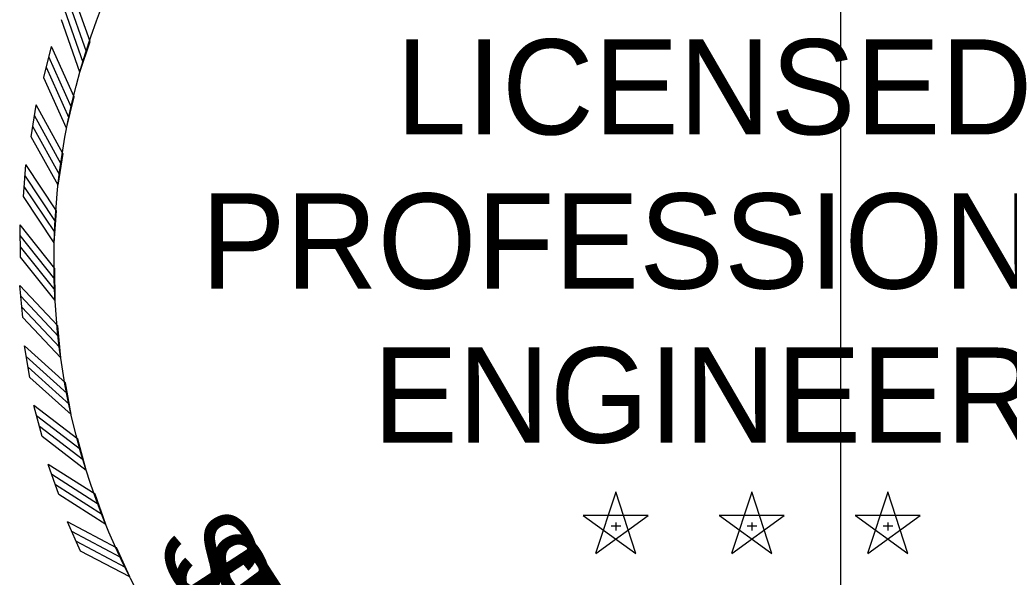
# Model space of a CAD drawing. Extents: x 18 to 14744716, y -5 to 1829144.
# Drawn here: x 17.6804 to 17.7967, y 10.8689 to 10.9344 of the extents above; entities that cross this region are included whole.
import ezdxf

# ---------------------------------------------------------------- set-up
doc = ezdxf.new("R2010")
doc.units = 0
for name, color, linetype in [('B_StampERBB', 7, 'Continuous'), ('B_StampHSS', 7, 'Continuous'), ('B_StampJSB', 7, 'Continuous'), ('B_StampSCR', 7, 'Continuous'), ('B_StampSFH', 7, 'Continuous'), ('R_No Plot', 7, 'Continuous')]:
    doc.layers.add(name, color=color, linetype=linetype)

msp = doc.modelspace()

# ---------------------------------------------------------------- linework, layer by layer
at = {"layer": 'B_StampERBB'}
for p, q in [((17.6832, 10.92765), (17.68409, 10.93131)), ((17.68744, 10.9283), (17.68864, 10.93188)), ((17.68588, 10.9217), (17.68678, 10.92537)), ((17.68171, 10.9207), (17.68229, 10.92442)), ((17.68487, 10.91499), (17.68546, 10.91873)), ((17.68079, 10.91365), (17.68107, 10.91741)), ((17.68442, 10.90823), (17.68469, 10.912)), ((17.68046, 10.90655), (17.68043, 10.91032)), ((17.68452, 10.90145), (17.68449, 10.90522)), ((17.68072, 10.89945), (17.68037, 10.90321)), ((17.68519, 10.8947), (17.68484, 10.89846)), ((17.68156, 10.8924), (17.68091, 10.89611)), ((17.68641, 10.88803), (17.68575, 10.89175)), ((17.68299, 10.88543), (17.68203, 10.88908)), ((17.68817, 10.88148), (17.68721, 10.88513)), ((17.68498, 10.87861), (17.68372, 10.88217)), ((17.69048, 10.8751), (17.68922, 10.87866)), ((17.75045, 10.87892), (17.74809, 10.87168)), ((17.7528, 10.87168), (17.75045, 10.87893)), ((17.76644, 10.87892), (17.76408, 10.87168)), ((17.76879, 10.87168), (17.76644, 10.87893)), ((17.78243, 10.87892), (17.78007, 10.87168)), ((17.78478, 10.87168), (17.78243, 10.87893)), ((17.68753, 10.87198), (17.68598, 10.87542)), ((17.75425, 10.87615), (17.74664, 10.87616)), ((17.74664, 10.87615), (17.7528, 10.87168)), ((17.7481, 10.87168), (17.75426, 10.87615)), ((17.75045, 10.87534), (17.75045, 10.87439)), ((17.77024, 10.87615), (17.76263, 10.87616)), ((17.76264, 10.87615), (17.76879, 10.87168)), ((17.76409, 10.87168), (17.77025, 10.87615)), ((17.76645, 10.87534), (17.76645, 10.87439)), ((17.78623, 10.87615), (17.77862, 10.87616)), ((17.77863, 10.87615), (17.78478, 10.87168)), ((17.78008, 10.87168), (17.78624, 10.87615)), ((17.78244, 10.87534), (17.78244, 10.87439)), ((17.7499, 10.87494), (17.75104, 10.87494)), ((17.7659, 10.87494), (17.76703, 10.87494)), ((17.78189, 10.87494), (17.78302, 10.87494)), ((17.6933, 10.86893), (17.69175, 10.87238))]:
    msp.add_line(p, q, dxfattribs=at)
for points in [[(17.68863, 10.93188), (17.68645, 10.93803)], [(17.68823, 10.93069), (17.68605, 10.93684)], [(17.68784, 10.92944), (17.68566, 10.93559)], [(17.68745, 10.92829), (17.68527, 10.93444)], [(17.68677, 10.92537), (17.68409, 10.93131)], [(17.68646, 10.92415), (17.68378, 10.9301)], [(17.68618, 10.92287), (17.6835, 10.92882)], [(17.68588, 10.92169), (17.6832, 10.92764)], [(17.68545, 10.91872), (17.68229, 10.92443)], [(17.68525, 10.91748), (17.68209, 10.92319)], [(17.68507, 10.91619), (17.68191, 10.92189)], [(17.68487, 10.91499), (17.68171, 10.92069)], [(17.68469, 10.91199), (17.68107, 10.91742)], [(17.68459, 10.91074), (17.68096, 10.91616)], [(17.68452, 10.90943), (17.6809, 10.91486)], [(17.68442, 10.90822), (17.6808, 10.91365)], [(17.68448, 10.90522), (17.68043, 10.91033)], [(17.68448, 10.90396), (17.68043, 10.90907)], [(17.68453, 10.90266), (17.68047, 10.90776)], [(17.68453, 10.90144), (17.68047, 10.90655)], [(17.68484, 10.89846), (17.68037, 10.90321)], [(17.68494, 10.8972), (17.68048, 10.90196)], [(17.68509, 10.8959), (17.68062, 10.90066)], [(17.68519, 10.89469), (17.68072, 10.89945)], [(17.68575, 10.89174), (17.68091, 10.89611)], [(17.68596, 10.8905), (17.68111, 10.89487)], [(17.68621, 10.88922), (17.68137, 10.89359)], [(17.68641, 10.88802), (17.68157, 10.89239)], [(17.68721, 10.88513), (17.68202, 10.88908)], [(17.68752, 10.88391), (17.68233, 10.88786)], [(17.68788, 10.88265), (17.68269, 10.88661)], [(17.68818, 10.88147), (17.68299, 10.88543)], [(17.68922, 10.87866), (17.68372, 10.88217)], [(17.68962, 10.87747), (17.68413, 10.88098)], [(17.69009, 10.87624), (17.68459, 10.87976)], [(17.69048, 10.8751), (17.68498, 10.87861)], [(17.69175, 10.87237), (17.68598, 10.87542)], [(17.69225, 10.87122), (17.68648, 10.87427)], [(17.69282, 10.87004), (17.68705, 10.87309)], [(17.6933, 10.86893), (17.68753, 10.87197)]]:
    msp.add_lwpolyline(points, dxfattribs=at)
at = {"layer": 'B_StampHSS'}
for p, q in [((17.6832, 10.92765), (17.68409, 10.93131)), ((17.68744, 10.9283), (17.68864, 10.93188)), ((17.68588, 10.9217), (17.68678, 10.92537)), ((17.68171, 10.9207), (17.68229, 10.92442)), ((17.68487, 10.91499), (17.68546, 10.91873)), ((17.68079, 10.91365), (17.68107, 10.91741)), ((17.68442, 10.90823), (17.68469, 10.912)), ((17.68046, 10.90655), (17.68043, 10.91032)), ((17.68452, 10.90145), (17.68449, 10.90522)), ((17.68072, 10.89945), (17.68037, 10.90321)), ((17.68519, 10.8947), (17.68484, 10.89846)), ((17.68156, 10.8924), (17.68091, 10.89611)), ((17.68641, 10.88803), (17.68575, 10.89175)), ((17.68299, 10.88543), (17.68203, 10.88908)), ((17.68817, 10.88148), (17.68721, 10.88513)), ((17.68498, 10.87861), (17.68372, 10.88217)), ((17.69048, 10.8751), (17.68922, 10.87866)), ((17.75045, 10.87892), (17.74809, 10.87168)), ((17.7528, 10.87168), (17.75045, 10.87893)), ((17.76644, 10.87892), (17.76408, 10.87168)), ((17.76879, 10.87168), (17.76644, 10.87893)), ((17.78243, 10.87892), (17.78007, 10.87168)), ((17.78478, 10.87168), (17.78243, 10.87893)), ((17.68753, 10.87198), (17.68598, 10.87542)), ((17.75425, 10.87615), (17.74664, 10.87616)), ((17.74664, 10.87615), (17.7528, 10.87168)), ((17.7481, 10.87168), (17.75426, 10.87615)), ((17.75045, 10.87534), (17.75045, 10.87439)), ((17.77024, 10.87615), (17.76263, 10.87616)), ((17.76264, 10.87615), (17.76879, 10.87168)), ((17.76409, 10.87168), (17.77025, 10.87615)), ((17.76645, 10.87534), (17.76645, 10.87439)), ((17.78623, 10.87615), (17.77862, 10.87616)), ((17.77863, 10.87615), (17.78478, 10.87168)), ((17.78008, 10.87168), (17.78624, 10.87615)), ((17.78244, 10.87534), (17.78244, 10.87439)), ((17.7499, 10.87494), (17.75104, 10.87494)), ((17.7659, 10.87494), (17.76703, 10.87494)), ((17.78189, 10.87494), (17.78302, 10.87494)), ((17.6933, 10.86893), (17.69175, 10.87238))]:
    msp.add_line(p, q, dxfattribs=at)
for points in [[(17.68863, 10.93188), (17.68645, 10.93803)], [(17.68823, 10.93069), (17.68605, 10.93684)], [(17.68784, 10.92944), (17.68566, 10.93559)], [(17.68745, 10.92829), (17.68527, 10.93444)], [(17.68677, 10.92537), (17.68409, 10.93131)], [(17.68646, 10.92415), (17.68378, 10.9301)], [(17.68618, 10.92287), (17.6835, 10.92882)], [(17.68588, 10.92169), (17.6832, 10.92764)], [(17.68545, 10.91872), (17.68229, 10.92443)], [(17.68525, 10.91748), (17.68209, 10.92319)], [(17.68507, 10.91619), (17.68191, 10.92189)], [(17.68487, 10.91499), (17.68171, 10.92069)], [(17.68469, 10.91199), (17.68107, 10.91742)], [(17.68459, 10.91074), (17.68096, 10.91616)], [(17.68452, 10.90943), (17.6809, 10.91486)], [(17.68442, 10.90822), (17.6808, 10.91365)], [(17.68448, 10.90522), (17.68043, 10.91033)], [(17.68448, 10.90396), (17.68043, 10.90907)], [(17.68453, 10.90266), (17.68047, 10.90776)], [(17.68453, 10.90144), (17.68047, 10.90655)], [(17.68484, 10.89846), (17.68037, 10.90321)], [(17.68494, 10.8972), (17.68048, 10.90196)], [(17.68509, 10.8959), (17.68062, 10.90066)], [(17.68519, 10.89469), (17.68072, 10.89945)], [(17.68575, 10.89174), (17.68091, 10.89611)], [(17.68596, 10.8905), (17.68111, 10.89487)], [(17.68621, 10.88922), (17.68137, 10.89359)], [(17.68641, 10.88802), (17.68157, 10.89239)], [(17.68721, 10.88513), (17.68202, 10.88908)], [(17.68752, 10.88391), (17.68233, 10.88786)], [(17.68788, 10.88265), (17.68269, 10.88661)], [(17.68818, 10.88147), (17.68299, 10.88543)], [(17.68922, 10.87866), (17.68372, 10.88217)], [(17.68962, 10.87747), (17.68413, 10.88098)], [(17.69009, 10.87624), (17.68459, 10.87976)], [(17.69048, 10.8751), (17.68498, 10.87861)], [(17.69175, 10.87237), (17.68598, 10.87542)], [(17.69225, 10.87122), (17.68648, 10.87427)], [(17.69282, 10.87004), (17.68705, 10.87309)], [(17.6933, 10.86893), (17.68753, 10.87197)]]:
    msp.add_lwpolyline(points, dxfattribs=at)
at = {"layer": 'B_StampJSB'}
for p, q in [((17.6832, 10.92765), (17.68409, 10.93131)), ((17.68744, 10.9283), (17.68864, 10.93188)), ((17.68588, 10.9217), (17.68678, 10.92537)), ((17.68171, 10.9207), (17.68229, 10.92442)), ((17.68487, 10.91499), (17.68546, 10.91873)), ((17.68079, 10.91365), (17.68107, 10.91741)), ((17.68442, 10.90823), (17.68469, 10.912)), ((17.68046, 10.90655), (17.68043, 10.91032)), ((17.68452, 10.90145), (17.68449, 10.90522)), ((17.68072, 10.89945), (17.68037, 10.90321)), ((17.68519, 10.8947), (17.68484, 10.89846)), ((17.68156, 10.8924), (17.68091, 10.89611)), ((17.68641, 10.88803), (17.68575, 10.89175)), ((17.68299, 10.88543), (17.68203, 10.88908)), ((17.68817, 10.88148), (17.68721, 10.88513)), ((17.68498, 10.87861), (17.68372, 10.88217)), ((17.69048, 10.8751), (17.68922, 10.87866)), ((17.75045, 10.87892), (17.74809, 10.87168)), ((17.7528, 10.87168), (17.75045, 10.87893)), ((17.76644, 10.87892), (17.76408, 10.87168)), ((17.76879, 10.87168), (17.76644, 10.87893)), ((17.78243, 10.87892), (17.78007, 10.87168)), ((17.78478, 10.87168), (17.78243, 10.87893)), ((17.68753, 10.87198), (17.68598, 10.87542)), ((17.75425, 10.87615), (17.74664, 10.87616)), ((17.74664, 10.87615), (17.7528, 10.87168)), ((17.7481, 10.87168), (17.75426, 10.87615)), ((17.75045, 10.87534), (17.75045, 10.87439)), ((17.77024, 10.87615), (17.76263, 10.87616)), ((17.76264, 10.87615), (17.76879, 10.87168)), ((17.76409, 10.87168), (17.77025, 10.87615)), ((17.76645, 10.87534), (17.76645, 10.87439)), ((17.78623, 10.87615), (17.77862, 10.87616)), ((17.77863, 10.87615), (17.78478, 10.87168)), ((17.78008, 10.87168), (17.78624, 10.87615)), ((17.78244, 10.87534), (17.78244, 10.87439)), ((17.7499, 10.87494), (17.75104, 10.87494)), ((17.7659, 10.87494), (17.76703, 10.87494)), ((17.78189, 10.87494), (17.78302, 10.87494)), ((17.6933, 10.86893), (17.69175, 10.87238))]:
    msp.add_line(p, q, dxfattribs=at)
for points in [[(17.68863, 10.93188), (17.68645, 10.93803)], [(17.68823, 10.93069), (17.68605, 10.93684)], [(17.68784, 10.92944), (17.68566, 10.93559)], [(17.68745, 10.92829), (17.68527, 10.93444)], [(17.68677, 10.92537), (17.68409, 10.93131)], [(17.68646, 10.92415), (17.68378, 10.9301)], [(17.68618, 10.92287), (17.6835, 10.92882)], [(17.68588, 10.92169), (17.6832, 10.92764)], [(17.68545, 10.91872), (17.68229, 10.92443)], [(17.68525, 10.91748), (17.68209, 10.92319)], [(17.68507, 10.91619), (17.68191, 10.92189)], [(17.68487, 10.91499), (17.68171, 10.92069)], [(17.68469, 10.91199), (17.68107, 10.91742)], [(17.68459, 10.91074), (17.68096, 10.91616)], [(17.68452, 10.90943), (17.6809, 10.91486)], [(17.68442, 10.90822), (17.6808, 10.91365)], [(17.68448, 10.90522), (17.68043, 10.91033)], [(17.68448, 10.90396), (17.68043, 10.90907)], [(17.68453, 10.90266), (17.68047, 10.90776)], [(17.68453, 10.90144), (17.68047, 10.90655)], [(17.68484, 10.89846), (17.68037, 10.90321)], [(17.68494, 10.8972), (17.68048, 10.90196)], [(17.68509, 10.8959), (17.68062, 10.90066)], [(17.68519, 10.89469), (17.68072, 10.89945)], [(17.68575, 10.89174), (17.68091, 10.89611)], [(17.68596, 10.8905), (17.68111, 10.89487)], [(17.68621, 10.88922), (17.68137, 10.89359)], [(17.68641, 10.88802), (17.68157, 10.89239)], [(17.68721, 10.88513), (17.68202, 10.88908)], [(17.68752, 10.88391), (17.68233, 10.88786)], [(17.68788, 10.88265), (17.68269, 10.88661)], [(17.68818, 10.88147), (17.68299, 10.88543)], [(17.68922, 10.87866), (17.68372, 10.88217)], [(17.68962, 10.87747), (17.68413, 10.88098)], [(17.69009, 10.87624), (17.68459, 10.87976)], [(17.69048, 10.8751), (17.68498, 10.87861)], [(17.69175, 10.87237), (17.68598, 10.87542)], [(17.69225, 10.87122), (17.68648, 10.87427)], [(17.69282, 10.87004), (17.68705, 10.87309)], [(17.6933, 10.86893), (17.68753, 10.87197)]]:
    msp.add_lwpolyline(points, dxfattribs=at)
msp.add_circle((17.76645, 10.90612), 0.08205, dxfattribs=at)
at = {"layer": 'B_StampSCR'}
for p, q in [((17.6832, 10.92765), (17.68409, 10.93131)), ((17.68744, 10.9283), (17.68864, 10.93188)), ((17.68588, 10.9217), (17.68678, 10.92537)), ((17.68171, 10.9207), (17.68229, 10.92442)), ((17.68487, 10.91499), (17.68546, 10.91873)), ((17.68079, 10.91365), (17.68107, 10.91741)), ((17.68442, 10.90823), (17.68469, 10.912)), ((17.68046, 10.90655), (17.68043, 10.91032)), ((17.68452, 10.90145), (17.68449, 10.90522)), ((17.68072, 10.89945), (17.68037, 10.90321)), ((17.68519, 10.8947), (17.68484, 10.89846)), ((17.68156, 10.8924), (17.68091, 10.89611)), ((17.68641, 10.88803), (17.68575, 10.89175)), ((17.68299, 10.88543), (17.68203, 10.88908)), ((17.68817, 10.88148), (17.68721, 10.88513)), ((17.68498, 10.87861), (17.68372, 10.88217)), ((17.69048, 10.8751), (17.68922, 10.87866)), ((17.75045, 10.87892), (17.74809, 10.87168)), ((17.7528, 10.87168), (17.75045, 10.87893)), ((17.76644, 10.87892), (17.76408, 10.87168)), ((17.76879, 10.87168), (17.76644, 10.87893)), ((17.78243, 10.87892), (17.78007, 10.87168)), ((17.78478, 10.87168), (17.78243, 10.87893)), ((17.68753, 10.87198), (17.68598, 10.87542)), ((17.75425, 10.87615), (17.74664, 10.87616)), ((17.74664, 10.87615), (17.7528, 10.87168)), ((17.7481, 10.87168), (17.75426, 10.87615)), ((17.75045, 10.87534), (17.75045, 10.87439)), ((17.77024, 10.87615), (17.76263, 10.87616)), ((17.76264, 10.87615), (17.76879, 10.87168)), ((17.76409, 10.87168), (17.77025, 10.87615)), ((17.76645, 10.87534), (17.76645, 10.87439)), ((17.78623, 10.87615), (17.77862, 10.87616)), ((17.77863, 10.87615), (17.78478, 10.87168)), ((17.78008, 10.87168), (17.78624, 10.87615)), ((17.78244, 10.87534), (17.78244, 10.87439)), ((17.7499, 10.87494), (17.75104, 10.87494)), ((17.7659, 10.87494), (17.76703, 10.87494)), ((17.78189, 10.87494), (17.78302, 10.87494)), ((17.6933, 10.86893), (17.69175, 10.87238))]:
    msp.add_line(p, q, dxfattribs=at)
for points in [[(17.68863, 10.93188), (17.68645, 10.93803)], [(17.68823, 10.93069), (17.68605, 10.93684)], [(17.68784, 10.92944), (17.68566, 10.93559)], [(17.68745, 10.92829), (17.68527, 10.93444)], [(17.68677, 10.92537), (17.68409, 10.93131)], [(17.68646, 10.92415), (17.68378, 10.9301)], [(17.68618, 10.92287), (17.6835, 10.92882)], [(17.68588, 10.92169), (17.6832, 10.92764)], [(17.68545, 10.91872), (17.68229, 10.92443)], [(17.68525, 10.91748), (17.68209, 10.92319)], [(17.68507, 10.91619), (17.68191, 10.92189)], [(17.68487, 10.91499), (17.68171, 10.92069)], [(17.68469, 10.91199), (17.68107, 10.91742)], [(17.68459, 10.91074), (17.68096, 10.91616)], [(17.68452, 10.90943), (17.6809, 10.91486)], [(17.68442, 10.90822), (17.6808, 10.91365)], [(17.68448, 10.90522), (17.68043, 10.91033)], [(17.68448, 10.90396), (17.68043, 10.90907)], [(17.68453, 10.90266), (17.68047, 10.90776)], [(17.68453, 10.90144), (17.68047, 10.90655)], [(17.68484, 10.89846), (17.68037, 10.90321)], [(17.68494, 10.8972), (17.68048, 10.90196)], [(17.68509, 10.8959), (17.68062, 10.90066)], [(17.68519, 10.89469), (17.68072, 10.89945)], [(17.68575, 10.89174), (17.68091, 10.89611)], [(17.68596, 10.8905), (17.68111, 10.89487)], [(17.68621, 10.88922), (17.68137, 10.89359)], [(17.68641, 10.88802), (17.68157, 10.89239)], [(17.68721, 10.88513), (17.68202, 10.88908)], [(17.68752, 10.88391), (17.68233, 10.88786)], [(17.68788, 10.88265), (17.68269, 10.88661)], [(17.68818, 10.88147), (17.68299, 10.88543)], [(17.68922, 10.87866), (17.68372, 10.88217)], [(17.68962, 10.87747), (17.68413, 10.88098)], [(17.69009, 10.87624), (17.68459, 10.87976)], [(17.69048, 10.8751), (17.68498, 10.87861)], [(17.69175, 10.87237), (17.68598, 10.87542)], [(17.69225, 10.87122), (17.68648, 10.87427)], [(17.69282, 10.87004), (17.68705, 10.87309)], [(17.6933, 10.86893), (17.68753, 10.87197)]]:
    msp.add_lwpolyline(points, dxfattribs=at)
at = {"layer": 'B_StampSFH'}
for p, q in [((17.6832, 10.92765), (17.68409, 10.93131)), ((17.68744, 10.9283), (17.68864, 10.93188)), ((17.68588, 10.9217), (17.68678, 10.92537)), ((17.68171, 10.9207), (17.68229, 10.92442)), ((17.68487, 10.91499), (17.68546, 10.91873)), ((17.68079, 10.91365), (17.68107, 10.91741)), ((17.68442, 10.90823), (17.68469, 10.912)), ((17.68046, 10.90655), (17.68043, 10.91032)), ((17.68452, 10.90145), (17.68449, 10.90522)), ((17.68072, 10.89945), (17.68037, 10.90321)), ((17.68519, 10.8947), (17.68484, 10.89846)), ((17.68156, 10.8924), (17.68091, 10.89611)), ((17.68641, 10.88803), (17.68575, 10.89175)), ((17.68299, 10.88543), (17.68203, 10.88908)), ((17.68817, 10.88148), (17.68721, 10.88513)), ((17.68498, 10.87861), (17.68372, 10.88217)), ((17.69048, 10.8751), (17.68922, 10.87866)), ((17.75045, 10.87892), (17.74809, 10.87168)), ((17.7528, 10.87168), (17.75045, 10.87893)), ((17.76644, 10.87892), (17.76408, 10.87168)), ((17.76879, 10.87168), (17.76644, 10.87893)), ((17.78243, 10.87892), (17.78007, 10.87168)), ((17.78478, 10.87168), (17.78243, 10.87893)), ((17.68753, 10.87198), (17.68598, 10.87542)), ((17.75425, 10.87615), (17.74664, 10.87616)), ((17.74664, 10.87615), (17.7528, 10.87168)), ((17.7481, 10.87168), (17.75426, 10.87615)), ((17.75045, 10.87534), (17.75045, 10.87439)), ((17.77024, 10.87615), (17.76263, 10.87616)), ((17.76264, 10.87615), (17.76879, 10.87168)), ((17.76409, 10.87168), (17.77025, 10.87615)), ((17.76645, 10.87534), (17.76645, 10.87439)), ((17.78623, 10.87615), (17.77862, 10.87616)), ((17.77863, 10.87615), (17.78478, 10.87168)), ((17.78008, 10.87168), (17.78624, 10.87615)), ((17.78244, 10.87534), (17.78244, 10.87439)), ((17.7499, 10.87494), (17.75104, 10.87494)), ((17.7659, 10.87494), (17.76703, 10.87494)), ((17.78189, 10.87494), (17.78302, 10.87494)), ((17.6933, 10.86893), (17.69175, 10.87238))]:
    msp.add_line(p, q, dxfattribs=at)
for points in [[(17.68863, 10.93188), (17.68645, 10.93803)], [(17.68823, 10.93069), (17.68605, 10.93684)], [(17.68784, 10.92944), (17.68566, 10.93559)], [(17.68745, 10.92829), (17.68527, 10.93444)], [(17.68677, 10.92537), (17.68409, 10.93131)], [(17.68646, 10.92415), (17.68378, 10.9301)], [(17.68618, 10.92287), (17.6835, 10.92882)], [(17.68588, 10.92169), (17.6832, 10.92764)], [(17.68545, 10.91872), (17.68229, 10.92443)], [(17.68525, 10.91748), (17.68209, 10.92319)], [(17.68507, 10.91619), (17.68191, 10.92189)], [(17.68487, 10.91499), (17.68171, 10.92069)], [(17.68469, 10.91199), (17.68107, 10.91742)], [(17.68459, 10.91074), (17.68096, 10.91616)], [(17.68452, 10.90943), (17.6809, 10.91486)], [(17.68442, 10.90822), (17.6808, 10.91365)], [(17.68448, 10.90522), (17.68043, 10.91033)], [(17.68448, 10.90396), (17.68043, 10.90907)], [(17.68453, 10.90266), (17.68047, 10.90776)], [(17.68453, 10.90144), (17.68047, 10.90655)], [(17.68484, 10.89846), (17.68037, 10.90321)], [(17.68494, 10.8972), (17.68048, 10.90196)], [(17.68509, 10.8959), (17.68062, 10.90066)], [(17.68519, 10.89469), (17.68072, 10.89945)], [(17.68575, 10.89174), (17.68091, 10.89611)], [(17.68596, 10.8905), (17.68111, 10.89487)], [(17.68621, 10.88922), (17.68137, 10.89359)], [(17.68641, 10.88802), (17.68157, 10.89239)], [(17.68721, 10.88513), (17.68202, 10.88908)], [(17.68752, 10.88391), (17.68233, 10.88786)], [(17.68788, 10.88265), (17.68269, 10.88661)], [(17.68818, 10.88147), (17.68299, 10.88543)], [(17.68922, 10.87866), (17.68372, 10.88217)], [(17.68962, 10.87747), (17.68413, 10.88098)], [(17.69009, 10.87624), (17.68459, 10.87976)], [(17.69048, 10.8751), (17.68498, 10.87861)], [(17.69175, 10.87237), (17.68598, 10.87542)], [(17.69225, 10.87122), (17.68648, 10.87427)], [(17.69282, 10.87004), (17.68705, 10.87309)], [(17.6933, 10.86893), (17.68753, 10.87197)]]:
    msp.add_lwpolyline(points, dxfattribs=at)
at = {"layer": 'R_No Plot'}
msp.add_lwpolyline([(17.77692, 16.62761), (51.77692, 16.62761), (51.77692, -5.37239), (17.77692, -5.37239)], close=True, dxfattribs=at)

# ---------------------------------------------------------------- texts
at = {"layer": 'B_StampERBB'}
for s, height, p in [('LICENSED', 0.011194, (17.72458, 10.92096)), ('PROFESSIONAL', 0.0111938, (17.70165, 10.90284)), ('ENGINEER', 0.011194, (17.72191, 10.88472))]:
    msp.add_text(s, height=height, dxfattribs=at).set_placement(p)
msp.add_text('E', height=0.01042, rotation=302.9873, dxfattribs=at).set_placement((17.69863, 10.86806))
at = {"layer": 'B_StampHSS'}
for s, height, p in [('LICENSED', 0.011194, (17.72458, 10.92096)), ('PROFESSIONAL', 0.0111938, (17.70165, 10.90284)), ('ENGINEER', 0.011194, (17.72191, 10.88472))]:
    msp.add_text(s, height=height, dxfattribs=at).set_placement(p)
msp.add_text('H', height=0.01042, rotation=306.2262, dxfattribs=at).set_placement((17.7, 10.86484))
at = {"layer": 'B_StampJSB'}
for s, height, p in [('LICENSED', 0.011194, (17.72458, 10.92096)), ('PROFESSIONAL', 0.0111938, (17.70165, 10.90284)), ('ENGINEER', 0.011194, (17.72191, 10.88472))]:
    msp.add_text(s, height=height, dxfattribs=at).set_placement(p)
at = {"layer": 'B_StampSCR'}
for s, height, p in [('LICENSED', 0.011194, (17.72458, 10.92096)), ('PROFESSIONAL', 0.0111938, (17.70165, 10.90284)), ('ENGINEER', 0.011194, (17.72191, 10.88472))]:
    msp.add_text(s, height=height, dxfattribs=at).set_placement(p)
for s, rotation, p in [('S', 298.6097, (17.69604, 10.87315)), ('H', 305.9057, (17.7008, 10.86443))]:
    msp.add_text(s, height=0.01042, rotation=rotation, dxfattribs=at).set_placement(p)
at = {"layer": 'B_StampSFH'}
for s, height, p in [('LICENSED', 0.011194, (17.72458, 10.92096)), ('PROFESSIONAL', 0.0111938, (17.70165, 10.90284)), ('ENGINEER', 0.011194, (17.72191, 10.88472))]:
    msp.add_text(s, height=height, dxfattribs=at).set_placement(p)
msp.add_text('S', height=0.01042, rotation=300.7985, dxfattribs=at).set_placement((17.69735, 10.87048))

doc.saveas('drawing.dxf')
